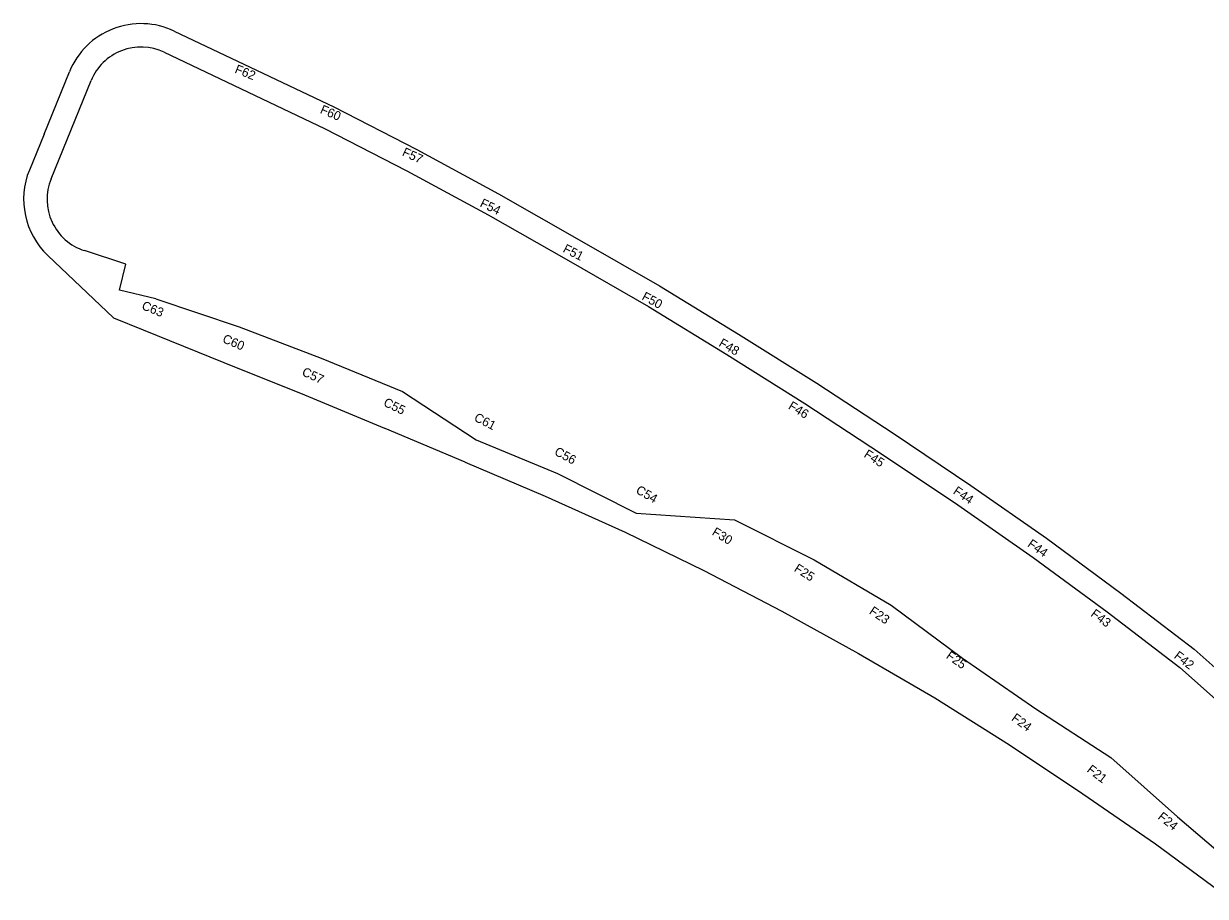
# Model space of a CAD drawing. Extents: x 2165700 to 2171741, y 206405 to 209505.
# Drawn here: x 2170405 to 2171061, y 207201 to 207685 of the extents above; entities that cross this region are included whole.
import ezdxf

# ---------------------------------------------------------------- set-up
doc = ezdxf.new("R2010")
doc.units = 0
for name, color, linetype in [('RD_PD_CstnLmt', 7, 'Continuous'), ('RD_PD_DR_ErosCtrl', 7, 'Continuous'), ('RD_PD_TX_CstnLmt', 7, 'Continuous')]:
    doc.layers.add(name, color=color, linetype=linetype)

msp = doc.modelspace()

# ---------------------------------------------------------------- linework, layer by layer
at = {"layer": 'RD_PD_CstnLmt'}
msp.add_line((2170420.18, 207599.16), (2170442.41, 207653.73), dxfattribs=at)
for points in [[(2170483.06, 207669.51), (2170572.17, 207627.19), (2170617.88, 207603.66), (2170663.04, 207579.23), (2170707.57, 207553.81), (2170751.96, 207528.33), (2170795.57, 207501.61), (2170838.83, 207474.44), (2170881.53, 207446.47), (2170923.88, 207418.04), (2170965.71, 207388.86), (2171006.74, 207358.6), (2171047.22, 207327.63), (2171085.37, 207293.75)], [(2170478.37, 207532.59), (2170458.13, 207537.26), (2170461.78, 207551.82), (2170438.71, 207559.3)], [(2170478.37, 207532.59), (2170524.7, 207516.94), (2170570.28, 207499.65), (2170615.37, 207481.04), (2170656.37, 207454.18), (2170701.51, 207435.43), (2170745.11, 207413.51), (2170799.76, 207409.68), (2170844.11, 207387.52), (2170886.76, 207362.39), (2170926.45, 207332.83), (2170967.15, 207304.73), (2171008.8, 207277.77), (2171045.8, 207244.75), (2171083.48, 207212.71)]]:
    msp.add_lwpolyline(points, dxfattribs=at)
for centre, start, end in [((2170470.19, 207642.41), 64.59357, 157.83882), ((2170447.97, 207587.84), 157.83882, 252.02668)]:
    msp.add_arc(centre, 30, start, end, dxfattribs=at)
at = {"layer": 'RD_PD_DR_ErosCtrl'}
for q in [(2170430.37, 207658.63), (2170408.14, 207604.06)]:
    msp.add_line((2170416.29, 207624.05), q, dxfattribs=at)
for points in [[(2170488.64, 207681.25), (2170530.76, 207661.22), (2170577.31, 207639.13), (2170623.29, 207615.48), (2170668.72, 207590.93), (2170713.51, 207565.37), (2170758.16, 207539.76), (2170802.03, 207512.89), (2170845.55, 207485.58), (2170888.49, 207457.44), (2170888.49, 207457.44), (2170931.1, 207428.85), (2170973.17, 207399.51), (2171014.44, 207369.07), (2171055.16, 207337.93), (2171093.53, 207303.87)], [(2170418.38, 207556.63), (2170454.96, 207521.96), (2170454.96, 207521.96), (2170471.34, 207515.34), (2170516.21, 207497.2), (2170560.91, 207479.2), (2170605.49, 207460.69), (2170605.51, 207460.67), (2170650.06, 207441.9), (2170650.13, 207441.86), (2170694.73, 207422.94), (2170739.03, 207402.91), (2170739.14, 207402.85), (2170782.76, 207381.51), (2170826.02, 207359.02), (2170868.78, 207335.44), (2170911.11, 207310.92), (2170952.49, 207284.79), (2170993.26, 207257.6), (2171033.68, 207229.74), (2171073.21, 207200.56)]]:
    msp.add_lwpolyline(points, dxfattribs=at)
for centre, start, end in [((2170470.19, 207642.41), 64.59357, 157.83882), ((2170447.97, 207587.84), 157.83882, 226.53076)]:
    msp.add_arc(centre, 43, start, end, dxfattribs=at)

# ---------------------------------------------------------------- texts
at = {"layer": 'RD_PD_TX_CstnLmt'}
for s, rotation, p in [('F62', 337.83882, (2170521.83, 207658.25)), ('F60', 336.70781, (2170569.25, 207635.87)), ('F57', 335.40563, (2170614.82, 207612.28)), ('F54', 334.10345, (2170658.02, 207584.01)), ('F51', 332.80127, (2170704.09, 207558.77)), ('C63', 337.83882, (2170470.14, 207526.91)), ('F50', 331.4991, (2170747.91, 207532.31)), ('C60', 336.70781, (2170515, 207508.54)), ('F48', 330.19692, (2170790.67, 207506.55)), ('C57', 335.40563, (2170559.11, 207490.22)), ('C55', 334.10345, (2170604.39, 207473.33)), ('F46', 328.89475, (2170829.27, 207471.68)), ('C61', 332.80127, (2170654.74, 207465.03)), ('C56', 331.4991, (2170699.32, 207446.17)), ('F45', 327.59257, (2170871.27, 207444.94)), ('C54', 330.19692, (2170744.57, 207424.88)), ('F44', 326.29039, (2170920.84, 207424.58)), ('F30', 328.89475, (2170786.89, 207401.66)), ('F44', 324.98821, (2170962.18, 207395.3)), ('F25', 327.59257, (2170832.5, 207381.49)), ('F23', 326.29039, (2170874.22, 207357.89)), ('F43', 323.68604, (2170997.28, 207356.59)), ('F25', 324.98821, (2170916.92, 207333.19)), ('F42', 322.38386, (2171043.53, 207333.32)), ('F24', 323.68604, (2170953.24, 207298.67)), ('F21', 322.38386, (2170995.17, 207270.15)), ('F24', 321.08168, (2171034.56, 207244.01))]:
    msp.add_text(s, height=5, rotation=rotation, dxfattribs=at).set_placement(p)

doc.saveas('drawing.dxf')
